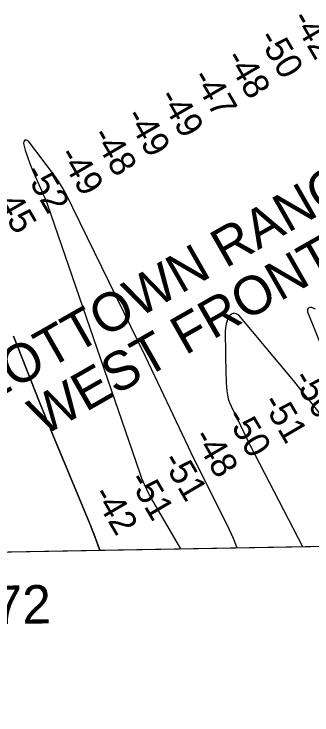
# Model space of a CAD drawing. Extents: x 3914892 to 3953151, y 242587 to 268572.
# Drawn here: x 3942793 to 3943565, y 248020 to 249840 of the extents above; entities that cross this region are included whole.
import ezdxf

# ---------------------------------------------------------------- set-up
doc = ezdxf.new("R2010")
doc.units = 0
for name, color, linetype in [('V-ANNO-TEXT', 7, 'Continuous'), ('V-CHAN-NAID', 7, 'Continuous'), ('V-GRID-FRAM', 7, 'Continuous'), ('V-RIVR-RANG', 7, 'Continuous'), ('V-TOPO-DPTH', 7, 'Continuous'), ('V-TOPO-MAJR', 7, 'Continuous'), ('V-TOPO-MINR', 7, 'Continuous')]:
    doc.layers.add(name, color=color, linetype=linetype)

msp = doc.modelspace()

# ---------------------------------------------------------------- linework, layer by layer
at = {"layer": 'V-GRID-FRAM'}
msp.add_lwpolyline([(3918836.6, 266200.2), (3950733.3, 266770.9), (3951066.5, 248591.3), (3919153.9, 248020.4), (3918836.6, 266200.2)], dxfattribs=at)
at = {"layer": 'V-TOPO-DPTH'}
for points in [[(3942349.6, 248435.9), (3943014.5, 248448), (3943013.9, 248449.8), (3943002.8, 248480.7), (3942999.1, 248490.7), (3942995.4, 248500.6), (3942991.5, 248510.5), (3942987.5, 248520.4), (3942893.5, 248747.5), (3942858.8, 248832.5), (3942824.6, 248917.7), (3942791.2, 249003.3)], [(3942791.2, 249003.3), (3942824.6, 248917.7), (3942858.8, 248832.5), (3942893.5, 248747.5), (3942987.5, 248520.4), (3942991.5, 248510.5), (3942995.4, 248500.6), (3942999.1, 248490.7), (3943002.8, 248480.7), (3943013.9, 248449.8), (3943014.5, 248448), (3944129.8, 248468.3)]]:
    msp.add_lwpolyline(points, dxfattribs=at)
at = {"layer": 'V-TOPO-MAJR'}
for points in [[(3943271.3, 248660.9), (3943258.1, 248688.1), (3943245.1, 248715.3), (3943133.4, 248950.6), (3942926.1, 249375.2), (3942917.2, 249390.6), (3942907.4, 249405.6), (3942897.1, 249420.2), (3942829.7, 249509.8), (3942824.7, 249511.9), (3942820.8, 249512), (3942818.3, 249508.8), (3942816.9, 249503.6), (3942821.8, 249486.1), (3942827.3, 249468.8), (3942833.6, 249451.7), (3942840.4, 249434.8), (3942863.6, 249381.4), (3942867.4, 249372.7), (3942871.2, 249364), (3942875, 249355.3), (3942878.8, 249346.6), (3943117.9, 248651), (3943120.3, 248642.8), (3943123, 248634.8), (3943126.1, 248626.9), (3943129.6, 248619.1), (3943142.2, 248593.1), (3943143.5, 248590.3), (3943145, 248587.5), (3943146.4, 248584.8), (3943148, 248582.1), (3943223.7, 248451.8)], [(3943574, 249073.4), (3943564.7, 249078), (3943559.1, 249077.8), (3943555.1, 249076.1), (3943553.3, 249072), (3943553.1, 249066.5), (3943616.6, 248910)], [(3943586.5, 248801.7), (3943563.6, 248830.8), (3943540.4, 248859.5), (3943516.9, 248888.1), (3943375.2, 249057.8), (3943368.6, 249061.8), (3943362.2, 249063.2), (3943356.2, 249060.7), (3943350.4, 249055.7), (3943345.9, 249046), (3943342.4, 249036), (3943340.7, 249025.6), (3943340, 249014.9), (3943341.9, 248903.8), (3943342.2, 248893.3), (3943342.6, 248882.8), (3943343.3, 248872.2), (3943344.2, 248861.7), (3943345.7, 248851.4), (3943348, 248841.2), (3943351.3, 248831.4), (3943355.3, 248821.7), (3943391.4, 248746.9), (3943394.5, 248740.6), (3943397.6, 248734.4), (3943400.7, 248728.1), (3943403.9, 248721.9), (3943540.7, 248457.6)], [(3943370.7, 248454.5), (3943370.4, 248455.8), (3943361.3, 248478.7), (3943351.1, 248501.3), (3943298, 248606.9), (3943284.6, 248633.9), (3943271.3, 248660.9)]]:
    msp.add_lwpolyline(points, dxfattribs=at)
at = {"layer": 'V-TOPO-MINR'}
msp.add_lwpolyline([(3942791.2, 249003.3), (3942824.6, 248917.7), (3942858.8, 248832.5), (3942893.5, 248747.5), (3942987.5, 248520.4), (3942991.5, 248510.5), (3942995.4, 248500.6), (3942999.1, 248490.7), (3943002.8, 248480.7), (3943013.9, 248449.8), (3943014.5, 248448)], dxfattribs=at)

# ---------------------------------------------------------------- texts
at = {"layer": 'V-ANNO-TEXT'}
msp.add_text('JOINS SHEET 72', height=100, rotation=1.025, dxfattribs=at).set_placement((3941826.6, 248239.2))
at = {"layer": 'V-CHAN-NAID'}
for s, p in [('PILOTTOWN RANGE A', (3942618, 248766.4)), ('WEST FRONT (1.0)', (3942868.7, 248743.1))]:
    msp.add_text(s, height=100, rotation=29.7053, dxfattribs=at).set_placement(p)
at = {"layer": 'V-RIVR-RANG'}
for s, rotation, p in [('-42', 300.2615, (3943509.8, 249828)), ('-50', 300.2615, (3943423.2, 249778.1)), ('-48', 300.2615, (3943337.9, 249725.8)), ('-47', 300.2615, (3943251.5, 249675.4)), ('-49', 300.2615, (3943165.3, 249624.8)), ('-49', 300.2615, (3943078.8, 249574.6)), ('-48', 300.2615, (3942991.9, 249525.1)), ('-49', 300.2615, (3942905.8, 249474.3)), ('-52', 300.2615, (3942816.8, 249428.4)), ('-45', 300.2615, (3942731.9, 249375.5)), ('-50', 300.3097, (3943512.6, 248895.1)), ('-51', 300.3097, (3943433.6, 248832.1)), ('-50', 300.3097, (3943339.7, 248794.6)), ('-48', 300.3097, (3943254.4, 248742.3)), ('-51', 300.3097, (3943174.2, 248681.3)), ('-51', 300.3097, (3943087.7, 248631.1)), ('-42', 300.3097, (3942994, 248593.3))]:
    msp.add_text(s, height=67, rotation=rotation, dxfattribs=at).set_placement(p)

doc.saveas('drawing.dxf')
